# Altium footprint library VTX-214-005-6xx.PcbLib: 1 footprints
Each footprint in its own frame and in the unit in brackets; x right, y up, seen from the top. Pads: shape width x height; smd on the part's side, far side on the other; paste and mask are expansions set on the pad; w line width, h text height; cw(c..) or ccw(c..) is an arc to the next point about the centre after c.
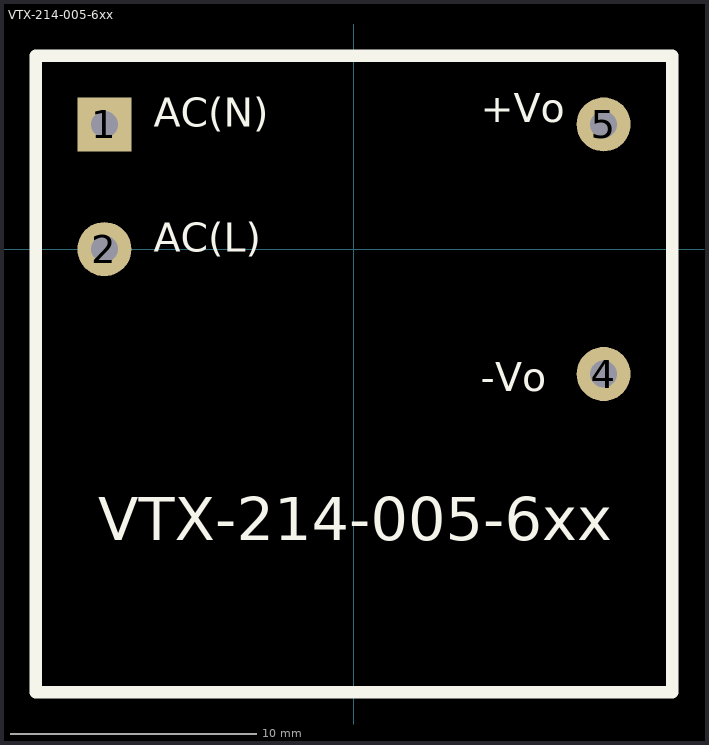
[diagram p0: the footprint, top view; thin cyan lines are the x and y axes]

## VTX-214-005-6xx [mm]
pads (4):
  rect 2.2x2.2 hole 1.1: 1(-10.16,5.08)
  round 2.2 hole 1.1: 2(-10.16,0) 4(10.16,-5.08) 5(10.16,5.08)
Top Overlay:
  lines w0.5: -12.95,-18.03 -12.95,7.87 12.95,7.87 12.95,-18.03 -12.95,-18.03
  text "-Vo" at 5.16,-6.177 h2
  text "+Vo" at 5.16,4.781 h2
  text "AC(L)" at -8.16,-0.486 h2
  text "AC(N)" at -8.16,4.594 h2
  text "VTX-214-005-6xx" at -10.414,-12.446 h3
